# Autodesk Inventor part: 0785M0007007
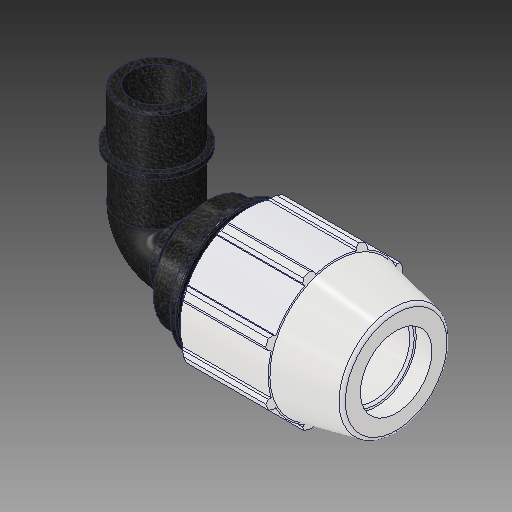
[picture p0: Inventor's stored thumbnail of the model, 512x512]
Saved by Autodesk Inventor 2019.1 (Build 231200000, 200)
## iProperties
Created: 2017-02
Part Number: 0785M0007007
Material: PVC-Piping
Description: PLASSON 90° ELBOW MALE ADAPTOR 3/4''-3/4''M
Document SubType Name: Modeling
Designer: KIM
Mass: 92.6774 g
Surface Area: 199.44 cm^2
Volume: 66.1981 cm^3
Density: 1.4 g/cm^3
Appearance: PTFE
Author: KIM
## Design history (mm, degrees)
derived "0785M0.ipt"
feature "Solid1::0785M0.ipt"
tag "TaggingFeature1"
body "Solid1"
other parameters: "d2" = 26.6, "d4" = 7.40833, "d5" = 22.225, "d7" = 54.102, "d9" = 12.7, "d11" = 2.96333, "d13" = 120 deg, "d14" = 39.9, "d15" = 12 deg, "d16" = 47.06874, "d18" = 1.33, "d19" = 35 deg, "d20" = 17.5 deg, "d21" = 50.31486, "d23" = 0, "d25" = 360 deg, "d27" = 1.08204, "d33" = 0.532, "d42" = 32.893, "d43" = 1.62306, "d46" = 0.798, "d51" = 88.9, "d68" = 2.96333, "d72" = 48.006, "d73" = 26.441, "d74" = 18.034, "d75" = 30.40715, "d76" = 18.5087, "d77" = 19.8374, "d79" = 10.5764, "d80" = 0.79323, "d83" = 0, "d84" = 0, "d91" = 40.5765, "d93" = 57.912, "d94" = 26.441, "d95" = 18.5087, "d96" = 8.89, "d97" = 50 deg, "d_" = 26.6, "E_" = 54.102, "A_" = 88.9, "l_" = 57.912, "l_2" = 18.034, "A_1" = 48.006, "G_" = 26.441
